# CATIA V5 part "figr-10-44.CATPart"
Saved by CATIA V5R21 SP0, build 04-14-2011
Part number: Part1
Bounding box of the stored display mesh (mm): x -80.563 to 63.541, y -72 to 69, z -55 to 56
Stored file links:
  D:\CATIA V5R21 E-RESOURCES\CATIA-V5R21\catia-v5r21-prt\c10-catia-v5r20-prt\c10-catia-v5r21-figr-10-44.CATPart
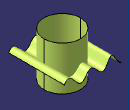
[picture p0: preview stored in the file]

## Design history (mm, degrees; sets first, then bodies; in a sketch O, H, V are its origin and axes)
Set1
  Sketch1 on xy-plane, origin (0, 0, 0), H (-1, 0, 0), V (0, -1, 0)
    circle A1 centre (0, 0) radius 45.985
  Extrude1: Element1 Sketch1, Lim1 56, Lim2 55, Direction xy-plane
  Sketch2 on zx-plane, origin (0, 0, 0), H (1, 0, 0), V (0, 0, -1)
    spline S1 through (-80.5635, 24.8913) (-73.6025, 19.8803) (-54.8525, -3.3629) (-35.1982, 19.8803) (-2.6271, -1.6506) (16.6996, 17.2854) (52.4104, -6.7877) (63.5409, 1.5862)
  Extrude2: Element1 Sketch2, Lim1 72, Lim2 69, Direction Sketch1.V
Body1 (main body)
